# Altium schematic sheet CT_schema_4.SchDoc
size 469 x 363 mm
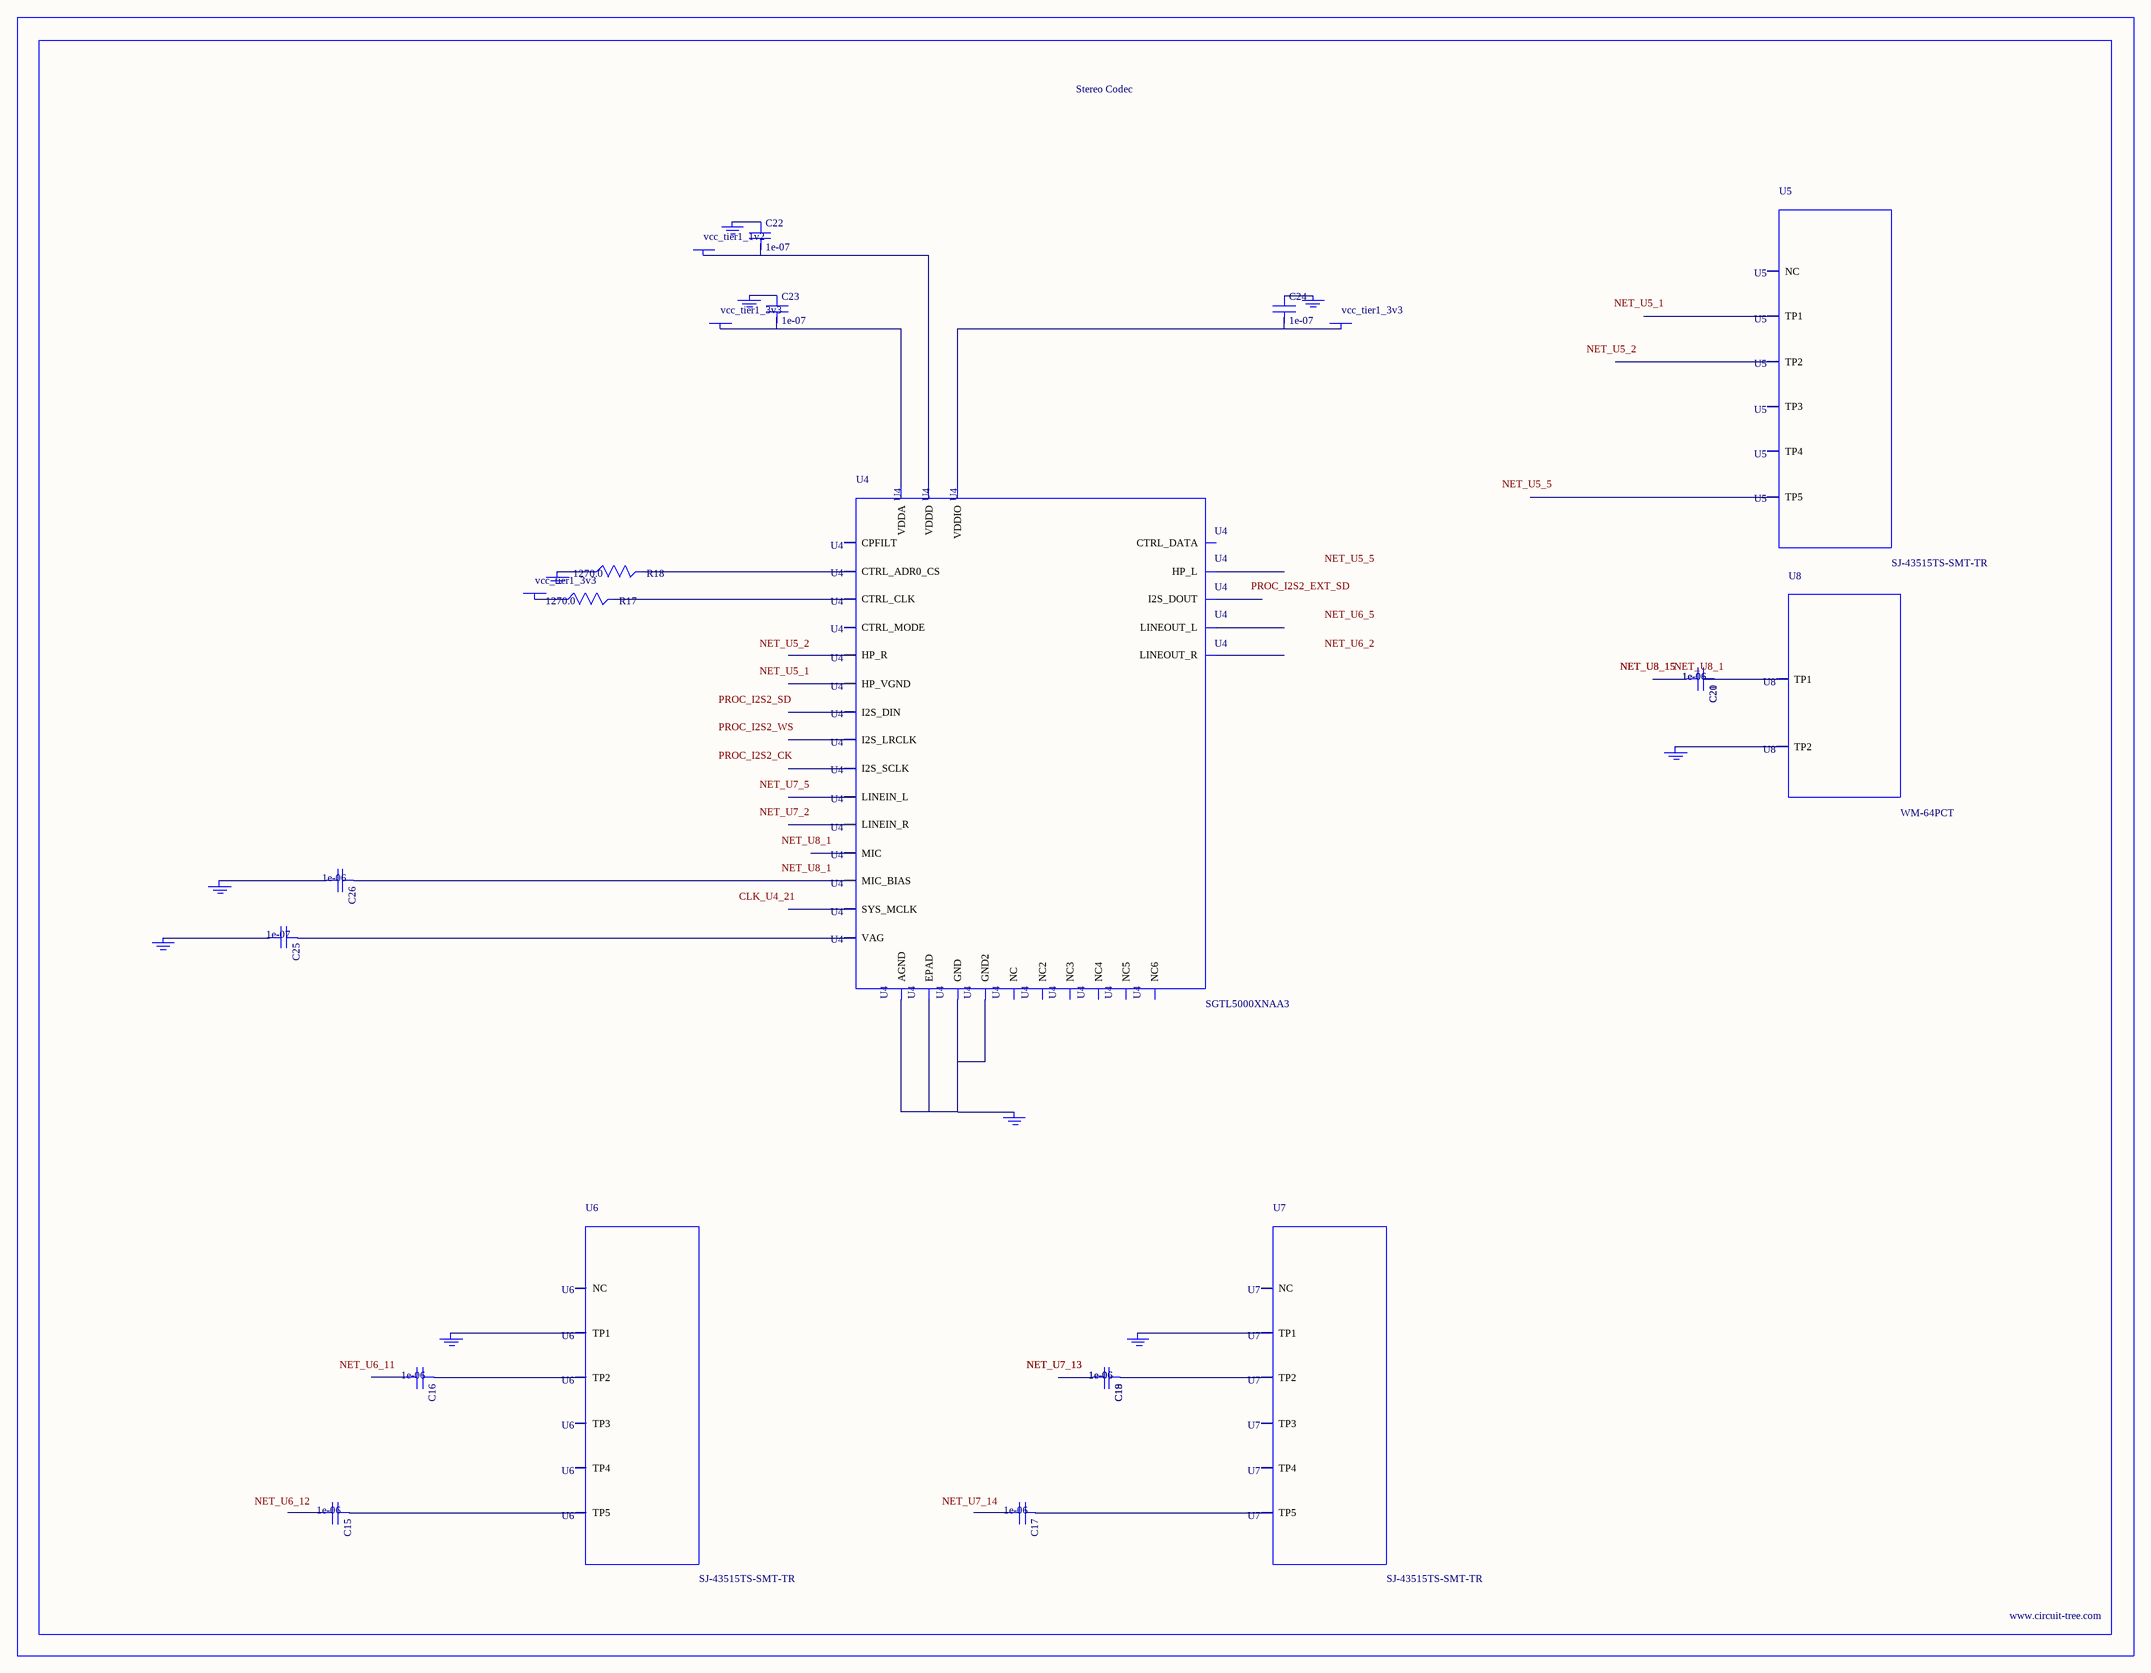
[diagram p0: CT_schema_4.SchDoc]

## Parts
BORDER3  (no value)
C15  1e-06  [C0603]
C16  1e-06  [C0603]
C17  1e-06  [C0603]
C18  1e-06  [C0603]
C19  1e-06  [C0603]
C20  1e-06  [C0603]
C21  1e-06  [C0603]
C22  1e-07  [C0402]
C23  1e-07  [C0402]
C24  1e-07  [C0402]
C25  1e-07  [C0402]
C26  1e-06  [C0603]
GND_INSTANCE_3_0  (no value)
GND_INSTANCE_3_1  (no value)
GND_INSTANCE_3_2  (no value)
GND_INSTANCE_3_3  (no value)
GND_INSTANCE_3_4  (no value)
GND_INSTANCE_3_5  (no value)
GND_INSTANCE_3_6  (no value)
GND_INSTANCE_3_7  (no value)
GND_INSTANCE_3_8  (no value)
GND_INSTANCE_3_9  (no value)
GND_INSTANCE_3_10  (no value)
POWER_INSTANCE_3_0  vcc_tier1_3v3
POWER_INSTANCE_3_1  vcc_tier1_3v3
POWER_INSTANCE_3_2  vcc_tier1_3v3
POWER_INSTANCE_3_3  vcc_tier1_1v2
R17  1270.0  [R0603]
R18  1270.0  [R0603]
U4  SGTL5000XNAA3  [QFN-32]
U5  SJ-43515TS-SMT-TR  [SJ-43515TS-SMT-TR]
U6  SJ-43515TS-SMT-TR  [SJ-43515TS-SMT-TR]
U7  SJ-43515TS-SMT-TR  [SJ-43515TS-SMT-TR]
U8  WM-64PCT  [WM-64PC]

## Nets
NetC15_1: C15.1 U6.5(TP5)
NetC16_1: C16.1 U6.2(TP2)
NetC17_1: C17.1 U7.5(TP5)
NetC18_1: C18.1 C19.1 U7.2(TP2)
NetC18_2: C18.2 C19.2
NetC20_1: C20.1 C21.1 U8.1(TP1)
NetC20_2: C20.2 C21.2
NetC22_1: C22.1 GND_INSTANCE_3_5.0(GND)
NetC22_2: C22.2 POWER_INSTANCE_3_3.0(PWR) U4.30(VDDD)
NetC23_1: C23.1 GND_INSTANCE_3_1.0(GND)
NetC23_2: C23.2 POWER_INSTANCE_3_0.0(PWR) U4.5(VDDA)
NetC24_1: C24.1 GND_INSTANCE_3_4.0(GND)
NetC24_2: C24.2 POWER_INSTANCE_3_1.0(PWR) U4.20(VDDIO)
NetC25_1: C25.1 U4.10(VAG)
NetC25_2: C25.2 GND_INSTANCE_3_2.0(GND)
NetC26_1: C26.1 U4.16(MIC_BIAS)
NetC26_2: C26.2 GND_INSTANCE_3_3.0(GND)
NetGND_INSTANCE_3_0_0: GND_INSTANCE_3_0.0(GND) U4.1(GND) U4.3(GND2) U4.7(AGND) U4.EXP(EPAD)
NetGND_INSTANCE_3_6_0: GND_INSTANCE_3_6.0(GND) R18.1
NetGND_INSTANCE_3_7_0: GND_INSTANCE_3_7.0(GND) U6.1(TP1)
NetGND_INSTANCE_3_8_0: GND_INSTANCE_3_8.0(GND) GND_INSTANCE_3_9.0(GND) U7.1(TP1)
NetGND_INSTANCE_3_10_0: GND_INSTANCE_3_10.0(GND) U8.2(TP2)
NetPOWER_INSTANCE_3_2_0: POWER_INSTANCE_3_2.0(PWR) R17.1
NetR17_2: R17.2 U4.29(CTRL_CLK)
NetR18_2: R18.2 U4.31(CTRL_ADR0_CS)

Not connected (* = marked no-connect by the designer): C15 2; C16 2; C17 2; U4 2(HP_R) 4(HP_VGND) 6(HP_L) 8(NC) 9(NC2) 11(LINEOUT_R) 12(LINEOUT_L) 13(LINEIN_R) 14(LINEIN_L) 15(MIC) 17(NC3) 18(CPFILT) 19(NC4) 21(SYS_MCLK) 22(NC5) 23(I2S_LRCLK) 24(I2S_SCLK) 25(I2S_DOUT) 26(I2S_DIN) 27(CTRL_DATA) 28(NC6) 32(CTRL_MODE); U5 1(TP1) 2(TP2) 3(TP3) 4(TP4) 5(TP5) 6(NC); U6 3(TP3) 4(TP4) 6(NC); U7 3(TP3) 4(TP4) 6(NC)

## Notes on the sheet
- Labels drawn without touching a wire or pin: CLK_U4_21, NET_U5_1, NET_U5_2, NET_U5_5, NET_U6_2, NET_U6_5, NET_U6_11, NET_U6_12, NET_U7_2, NET_U7_5, NET_U7_14, NET_U8_1, PROC_I2S2_CK, PROC_I2S2_EXT_SD, PROC_I2S2_SD, PROC_I2S2_WS

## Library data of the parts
BORDER3 = BORDER_PAGE3
C15-C21 C26 = C0603C105K3RACTU
C22-C25 = C0402C104K3RACTU
GND_INSTANCE_3_0-GND_INSTANCE_3_10 = GND
POWER_INSTANCE_3_0-POWER_INSTANCE_3_3 = PWR
R17 R18 = RC0603FR-071K27L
